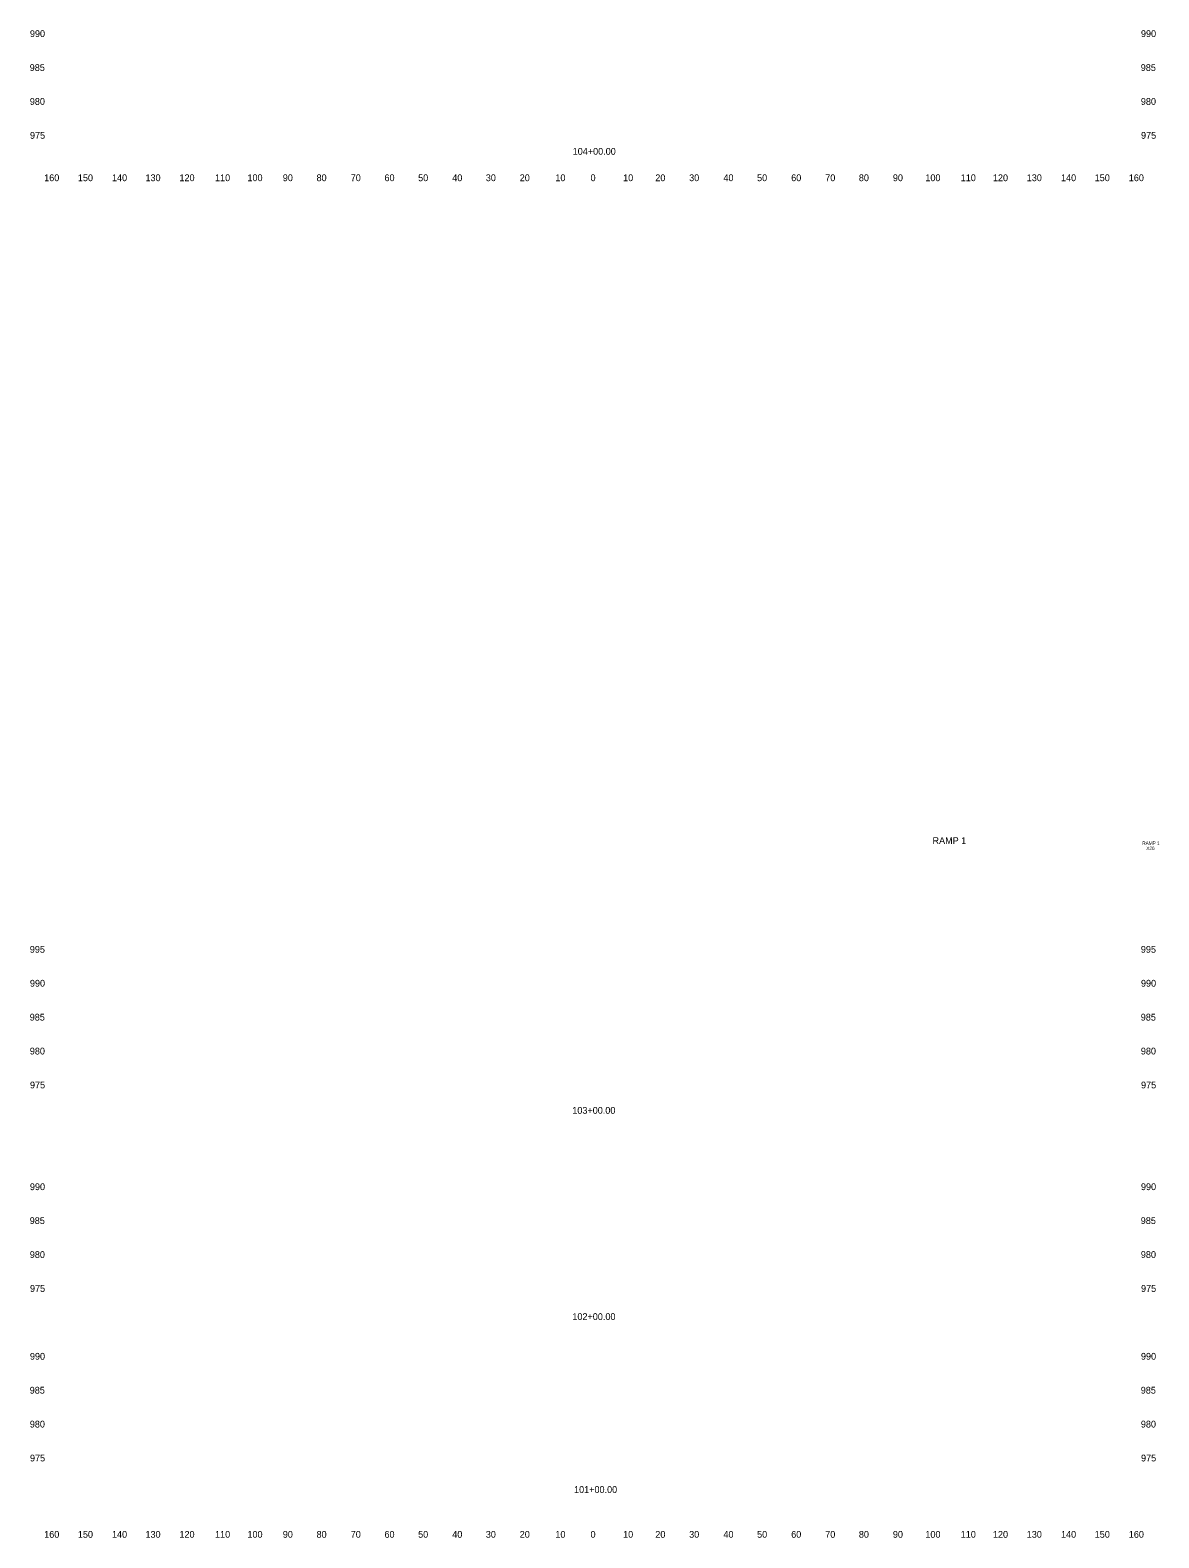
# Model space of a CAD drawing. Extents: x 4994 to 7869, y 4997 to 8804.
# Drawn here: x 6024 to 6357, y 6997.5 to 7442 of the extents above; entities that cross this region are included whole.
import ezdxf

# ---------------------------------------------------------------- set-up
doc = ezdxf.new("R2010")
doc.units = 0
for name, color, linetype in [('RD_SHT_ID', 7, 'Continuous'), ('RD_XS_TX_Offset', 7, 'Continuous'), ('RD_XS_TX_Station', 7, 'Continuous')]:
    doc.layers.add(name, color=color, linetype=linetype)

msp = doc.modelspace()

# ---------------------------------------------------------------- texts
at = {"layer": 'RD_SHT_ID'}
for s, height, p in [('RAMP 1', 2, (6290.19, 7202.06)), ('RAMP 1', 1, (6352.06, 7201.8)), ('X26', 1, (6353.26, 7200.3))]:
    msp.add_text(s, height=height, dxfattribs=at).set_placement(p)
at = {"layer": 'RD_XS_TX_Offset'}
for s, p in [('990', (6023.89, 7440)), ('990', (6351.69, 7440)), ('985', (6023.83, 7430)), ('985', (6351.63, 7430)), ('980', (6023.86, 7420)), ('980', (6351.66, 7420)), ('975', (6023.91, 7410)), ('975', (6351.71, 7410)), ('160', (6028.1, 7397.5)), ('150', (6038.04, 7397.5)), ('140', (6048.1, 7397.5)), ('130', (6057.99, 7397.5)), ('120', (6068.01, 7397.5)), ('110', (6078.51, 7397.5)), ('100', (6088.07, 7397.5)), ('90', (6098.5, 7397.5)), ('80', (6108.46, 7397.5)), ('70', (6118.54, 7397.5)), ('60', (6128.5, 7397.5)), ('50', (6138.43, 7397.5)), ('40', (6148.5, 7397.5)), ('30', (6158.39, 7397.5)), ('20', (6168.4, 7397.5)), ('10', (6178.91, 7397.5)), ('0', (6189.3, 7397.5)), ('0', (6189.3, 7397.5)), ('10', (6198.91, 7397.5)), ('20', (6208.4, 7397.5)), ('30', (6218.39, 7397.5)), ('40', (6228.5, 7397.5)), ('50', (6238.43, 7397.5)), ('60', (6248.5, 7397.5)), ('70', (6258.54, 7397.5)), ('80', (6268.46, 7397.5)), ('90', (6278.5, 7397.5)), ('100', (6288.07, 7397.5)), ('110', (6298.51, 7397.5)), ('120', (6308.01, 7397.5)), ('130', (6317.99, 7397.5)), ('140', (6328.1, 7397.5)), ('150', (6338.04, 7397.5)), ('160', (6348.1, 7397.5)), ('995', (6023.86, 7170)), ('995', (6351.66, 7170)), ('990', (6023.89, 7160)), ('990', (6351.69, 7160)), ('985', (6023.83, 7150)), ('985', (6351.63, 7150)), ('980', (6023.86, 7140)), ('980', (6351.66, 7140)), ('975', (6023.91, 7130)), ('975', (6351.71, 7130)), ('990', (6023.89, 7100)), ('990', (6351.69, 7100)), ('985', (6023.83, 7090)), ('985', (6351.63, 7090)), ('980', (6023.86, 7080)), ('980', (6351.66, 7080)), ('975', (6023.91, 7070)), ('975', (6351.71, 7070)), ('990', (6023.89, 7050)), ('990', (6351.69, 7050)), ('985', (6023.83, 7040)), ('985', (6351.63, 7040)), ('980', (6023.86, 7030)), ('980', (6351.66, 7030)), ('975', (6023.91, 7020)), ('975', (6351.71, 7020)), ('160', (6028.1, 6997.5)), ('150', (6038.04, 6997.5)), ('140', (6048.1, 6997.5)), ('130', (6057.99, 6997.5)), ('120', (6068.01, 6997.5)), ('110', (6078.51, 6997.5)), ('100', (6088.07, 6997.5)), ('90', (6098.5, 6997.5)), ('80', (6108.46, 6997.5)), ('70', (6118.54, 6997.5)), ('60', (6128.5, 6997.5)), ('50', (6138.43, 6997.5)), ('40', (6148.5, 6997.5)), ('30', (6158.39, 6997.5)), ('20', (6168.4, 6997.5)), ('10', (6178.91, 6997.5)), ('0', (6189.3, 6997.5)), ('0', (6189.3, 6997.5)), ('10', (6198.91, 6997.5)), ('20', (6208.4, 6997.5)), ('30', (6218.39, 6997.5)), ('40', (6228.5, 6997.5)), ('50', (6238.43, 6997.5)), ('60', (6248.5, 6997.5)), ('70', (6258.54, 6997.5)), ('80', (6268.46, 6997.5)), ('90', (6278.5, 6997.5)), ('100', (6288.07, 6997.5)), ('110', (6298.51, 6997.5)), ('120', (6308.01, 6997.5)), ('130', (6317.99, 6997.5)), ('140', (6328.1, 6997.5)), ('150', (6338.04, 6997.5)), ('160', (6348.1, 6997.5))]:
    msp.add_text(s, height=2, dxfattribs=at).set_placement(p)
at = {"layer": 'RD_XS_TX_Station'}
for s, p in [('104+00.00', (6184.02, 7405.29)), ('103+00.00', (6183.91, 7122.52)), ('102+00.00', (6183.93, 7061.71)), ('101+00.00', (6184.43, 7010.72))]:
    msp.add_text(s, height=2, dxfattribs=at).set_placement(p)

doc.saveas('drawing.dxf')
